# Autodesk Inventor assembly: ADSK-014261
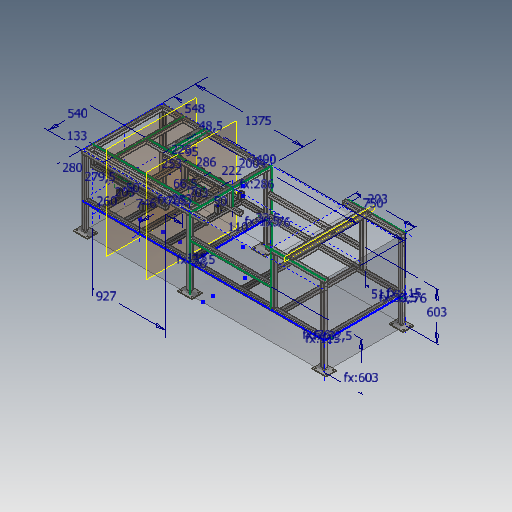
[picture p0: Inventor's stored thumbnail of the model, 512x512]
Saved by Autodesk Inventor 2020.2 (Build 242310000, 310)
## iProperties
_SolveAssemblyDoc: Frame Generator Solve Assembly
_Version: 15.0.0
Created: 2019-10
Part Number: ADSK-014261
Document SubType Name: Assembly
Designer: lutzd
Mass: 2.34801e+07 g
Surface Area: 272440 cm^2
Volume: 2.99487e+06 cm^3
Density: 7.8401 g/cm^3
VLDS_Profile: Default Assembly
VLDS_TimeStamp: 2016-07-29
VLDS_FailCnt: 0
VLDS_AcceptCnt: 0
Dimensions: 1113,3x1072x3207,8 mm
Mass: 23480,091 kg
DocNumber: ADSK-014261
Folder: 01 - Themengebiete\Simplification\01 - Packaging machine\
VDS_Category: 3D Komponenten
VDS_NumSchm: Autodesk
Title: Frame
Author: lutzd
Revision Number: -
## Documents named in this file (5)
- D:\07 - DEMODATEN\OTX 2019 - Dataset - UPDATE - Dez2019\Designs\07-Packing machine\ADSK-014261.iam
- D:\07 - DEMODATEN\OTX 2019 - Dataset - UPDATE - Dez2019\Designs\07-Packing machine\Parts\ADSK-014260.ipt
- D:\07 - DEMODATEN\OTX 2019 - Dataset - UPDATE - Dez2019\Designs\07-Packing machine\ADSK-014261\Frame\ADSK-014262.iam
- D:\07 - DEMODATEN\OTX 2019 - Dataset - UPDATE - Dez2019\Designs\07-Packing machine\Parts\ADSK-011287.ipt
- D:\07 - DEMODATEN\OTX 2019 - Dataset - UPDATE - Dez2019\Designs\07-Packing machine\Parts\ADSK-011288.ipt
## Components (14 placed, 4 different names)
1. ADSK-014260:1 — Fluchtend:6, Fluchtend:9, Fluchtend:11, Fluchtend:14, Fluchtend:15, Fluchtend:17
2. ADSK-014262:1 [sub-assembly] — Passend:19, Passend:28, Passend:40, Passend:41, Fluchtend:12, Passend:42, Passend:52, Passend:53, Passend:54, Fluchtend:16, Passend:56, Passend:57, Fluchtend:18, Fluchtend:19
3. ADSK-011287:5 — Fluchtend:6, Passend:28
4. ADSK-011288:5 — Passend:19
5. ADSK-011287:8 — Fluchtend:9, Passend:42
6. ADSK-011288:8 — Passend:40
7. ADSK-011287:9 — Fluchtend:11, Fluchtend:12
8. ADSK-011288:9 — Passend:41
9. ADSK-011287:10 — Fluchtend:15, Fluchtend:16
10. ADSK-011288:10 — Passend:52
11. ADSK-011287:11 — Fluchtend:17, Passend:57
12. ADSK-011288:11 — Passend:53
13. ADSK-011287:12 — Fluchtend:14, Passend:56
14. ADSK-011288:12 — Passend:54
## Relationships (20: Mate 10, Flush 10)
- Passend:19 [Mate]: ADSK-014262:1 ↔ ADSK-011288:5
- Fluchtend:6 [Flush]: ADSK-014260:1 ↔ ADSK-011287:5
- Passend:28 [Mate]: ADSK-014262:1 ↔ ADSK-011287:5
- Passend:40 [Mate]: ADSK-014262:1 ↔ ADSK-011288:8
- Passend:41 [Mate]: ADSK-014262:1 ↔ ADSK-011288:9
- Fluchtend:9 [Flush]: ADSK-014260:1 ↔ ADSK-011287:8
- Fluchtend:11 [Flush]: ADSK-014260:1 ↔ ADSK-011287:9
- Fluchtend:12 [Flush]: ADSK-014262:1 ↔ ADSK-011287:9
- Passend:42 [Mate]: ADSK-014262:1 ↔ ADSK-011287:8
- Passend:52 [Mate]: ADSK-014262:1 ↔ ADSK-011288:10
- Passend:53 [Mate]: ADSK-014262:1 ↔ ADSK-011288:11
- Passend:54 [Mate]: ADSK-014262:1 ↔ ADSK-011288:12
- Fluchtend:14 [Flush]: ADSK-014260:1 ↔ ADSK-011287:12
- Fluchtend:15 [Flush]: ADSK-014260:1 ↔ ADSK-011287:10
- Fluchtend:16 [Flush]: ADSK-014262:1 ↔ ADSK-011287:10
- Passend:56 [Mate]: ADSK-014262:1 ↔ ADSK-011287:12
- Fluchtend:17 [Flush]: ADSK-014260:1 ↔ ADSK-011287:11
- Passend:57 [Mate]: ADSK-014262:1 ↔ ADSK-011287:11
- Fluchtend:18 [Flush]: ADSK-014262:1
- Fluchtend:19 [Flush]: ADSK-014262:1
## Named parameters: d13_d51_d44 = 0, d14_d52_d45 = 0, d15_d53_d46 = 0, d40_d55_d50 = 45 mm, d41_d56_d47 = 0, d42_d57_d49 = 0, d43_d55_d50 = 45 mm, d44_d56_d47 = 0, d45_d57_d49 = 0, d55_d13_d51_d44 = 0, d56_d14_d52_d45 = 0, d57_d15_d53_d46 = 0, d58_d13_d51_d44 = 0, d59_d14_d52_d45 = 0, d60_d15_d53_d46 = 0, d61_d13_d51_d44 = 0, d62_d14_d52_d45 = 0, d63_d15_d53_d46 = 0
